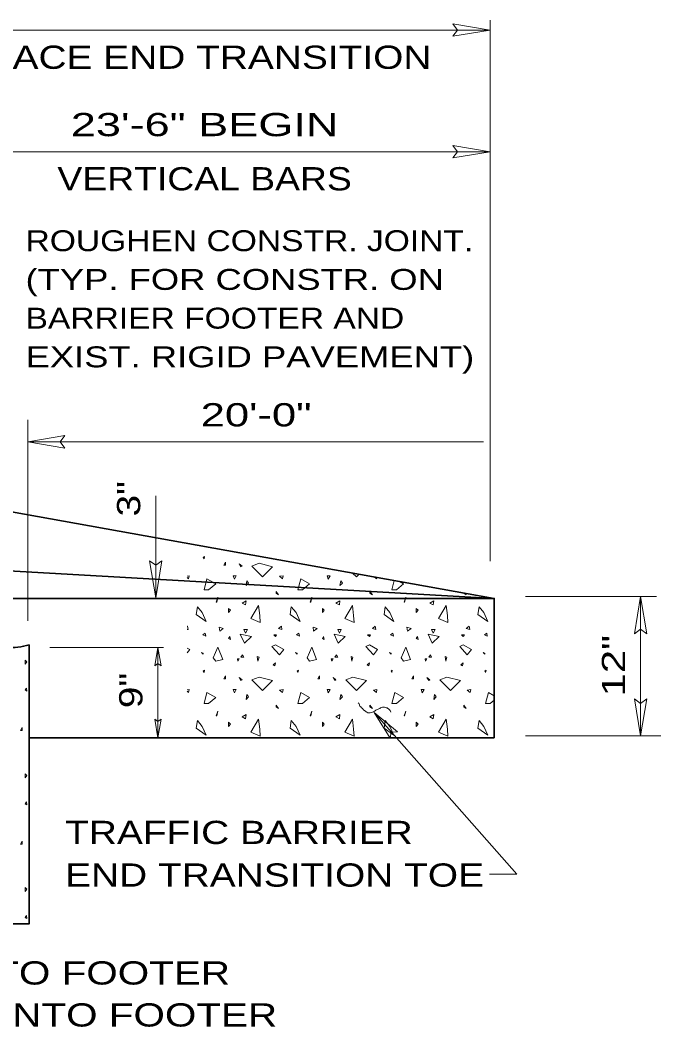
# Model space of a CAD drawing. Extents: x -15.1 to -7.9, y 13.6 to 23.8.
# Drawn here: x -9.819 to -8.165, y 17.024 to 19.625 of the extents above; entities that cross this region are included whole.
import ezdxf
from ezdxf.enums import TextEntityAlignment as Align

# ---------------------------------------------------------------- set-up
doc = ezdxf.new("R2010")
doc.units = 0
doc.header["$LTSCALE"] = 0.024
for name, color, linetype, lineweight in [('1', 7, 'Continuous', 35), ('10', 7, 'Continuous', 13), ('12', 7, 'Continuous', 53), ('6', 7, 'Continuous', 13)]:
    doc.layers.add(name, color=color, linetype=linetype, lineweight=lineweight)

msp = doc.modelspace()

# ---------------------------------------------------------------- linework, layer by layer
at = {"layer": '1'}
for q in [(-11.27267, 18.28367), (-11.26617, 18.13083)]:
    msp.add_line((-8.59533, 18.13083), q, dxfattribs=at)
for points in [[(-8.59533, 17.77083), (-8.59533, 18.13083), (-11.26567, 18.61083)], [(-8.59533, 17.77083), (-9.7955, 17.77083), (-9.7955, 18.01083)], [(-9.7955, 17.77083), (-9.7955, 17.29067), (-11.26567, 17.29067)]]:
    msp.add_lwpolyline(points, dxfattribs=at)
msp.add_spline([(-9.7955, 18.01083), (-9.85317, 18.006), (-9.89217, 18.019), (-9.94717, 18.00933), (-9.9505, 18.00933), (-9.9925, 18.00933), (-10.02167, 18.01567), (-10.06383, 18.019), (-10.10283, 18.02217), (-10.13517, 18.0125), (-10.17083, 18.00283), (-10.213, 18.00283), (-10.2485, 18.006), (-10.2875, 18.00933), (-10.31983, 18.0125), (-10.3685, 18.01567), (-10.42033, 18.01567), (-10.456, 18.0125), (-10.48183, 18.0125), (-10.511, 18.0125), (-10.52083, 18.01567), (-10.57917, 18.02867), (-10.605, 18.03517), (-10.644, 18.03183), (-10.69583, 18.02867), (-10.72817, 18.0255), (-10.7605, 18.02867), (-10.81567, 18.02867), (-10.874, 18.03517), (-10.93233, 18.03517), (-10.98417, 18.03183), (-11.02633, 18.02867), (-11.07817, 18.03833), (-11.14617, 18.05117), (-11.2045, 18.048), (-11.23367, 18.0415), (-11.25967, 18.03517), (-11.26617, 18.03183)], degree=3, dxfattribs=at)
at = {"layer": '10'}
for p, q in [((-8.702, 19.61517), (-8.606, 19.59917)), ((-8.702, 19.61517), (-8.69, 19.59917)), ((-8.606, 18.227), (-8.606, 19.625)), ((-13.76867, 19.59917), (-8.606, 19.59917)), ((-8.702, 19.58317), (-8.606, 19.59917)), ((-8.702, 19.58317), (-8.69, 19.59917)), ((-8.702, 19.30117), (-8.606, 19.28517)), ((-8.702, 19.30117), (-8.69, 19.28517)), ((-10.09083, 19.28517), (-8.606, 19.28517)), ((-8.702, 19.26917), (-8.606, 19.28517)), ((-8.702, 19.26917), (-8.69, 19.28517)), ((-9.7995, 18.07283), (-9.7995, 18.5925)), ((-9.7035, 18.5515), (-9.7995, 18.5355)), ((-9.7035, 18.5515), (-9.7155, 18.5355)), ((-9.7995, 18.5355), (-8.62317, 18.5355)), ((-9.7035, 18.5195), (-9.7995, 18.5355)), ((-9.7035, 18.5195), (-9.7155, 18.5355)), ((-9.46917, 18.1325), (-9.46917, 18.39583)), ((-9.48517, 18.2285), (-9.46917, 18.1325)), ((-9.48517, 18.2285), (-9.46917, 18.2165)), ((-9.45317, 18.2285), (-9.46917, 18.1325)), ((-9.45317, 18.2285), (-9.46917, 18.2165)), ((-8.51467, 18.136), (-8.17667, 18.136)), ((-8.23367, 18.03983), (-8.21767, 18.136)), ((-8.21767, 17.77583), (-8.21767, 18.136)), ((-8.20167, 18.03983), (-8.21767, 18.136)), ((-8.23367, 18.03983), (-8.21767, 18.05183)), ((-8.20167, 18.03983), (-8.21767, 18.05183)), ((-9.7425, 18.0045), (-9.44933, 18.0045)), ((-9.4715, 17.9565), (-9.4635, 18.0045)), ((-9.4635, 18.0045), (-9.4635, 17.77083)), ((-9.4555, 17.9565), (-9.4635, 18.0045)), ((-9.4715, 17.9565), (-9.4635, 17.9625)), ((-9.4555, 17.9565), (-9.4635, 17.9625)), ((-8.23367, 17.87183), (-8.21767, 17.77583)), ((-8.23367, 17.87183), (-8.21767, 17.85983)), ((-8.20167, 17.87183), (-8.21767, 17.77583)), ((-8.20167, 17.87183), (-8.21767, 17.85983)), ((-9.4715, 17.81883), (-9.4635, 17.77083)), ((-9.4715, 17.81883), (-9.4635, 17.81283)), ((-9.4555, 17.81883), (-9.4635, 17.77083)), ((-9.4555, 17.81883), (-9.4635, 17.81283)), ((-8.53683, 17.41833), (-8.90567, 17.83583)), ((-8.86433, 17.76983), (-8.90567, 17.83583)), ((-8.84517, 17.78667), (-8.90567, 17.83583)), ((-8.86433, 17.76983), (-8.86117, 17.7855)), ((-8.84517, 17.78667), (-8.86117, 17.7855)), ((-8.51467, 17.77583), (-8.16533, 17.77583)), ((-8.6075, 17.41833), (-8.53683, 17.41833))]:
    msp.add_line(p, q, dxfattribs=at)
msp.add_spline([(-8.86267, 17.837), (-8.864, 17.84133), (-8.867, 17.84417), (-8.86983, 17.847), (-8.87417, 17.8485), (-8.8785, 17.84983), (-8.88417, 17.84983), (-8.893, 17.84567), (-8.89717, 17.84417), (-8.9045, 17.83983), (-8.916, 17.8355), (-8.92183, 17.8355), (-8.92617, 17.83833), (-8.93183, 17.84267), (-8.93767, 17.8485), (-8.942, 17.85283), (-8.94483, 17.86), (-8.94633, 17.8615)], degree=3, dxfattribs=at)
at = {"layer": '6'}
for points in [[(-9.34317, 18.23967), (-9.34633, 18.23683), (-9.3445, 18.2335)], [(-9.28867, 18.2245), (-9.293, 18.217), (-9.28867, 18.217)], [(-9.24917, 18.21267), (-9.24633, 18.21417), (-9.25383, 18.22017)], [(-9.20233, 18.22167), (-9.16733, 18.21267), (-9.19333, 18.18667), (-9.22067, 18.21417)], [(-9.33267, 18.15317), (-9.31433, 18.16867), (-9.337, 18.182), (-9.3445, 18.15317)], [(-9.269, 18.18967), (-9.266, 18.18067), (-9.26133, 18.18967)], [(-9.14933, 18.18817), (-9.14183, 18.182), (-9.14033, 18.18967)], [(-9.09033, 18.15317), (-9.072, 18.16867), (-9.09467, 18.182), (-9.10217, 18.15317)], [(-9.02667, 18.18967), (-9.02367, 18.18067), (-9.019, 18.18967)], [(-9.234, 18.17633), (-9.23583, 18.164), (-9.22967, 18.17017)], [(-8.99167, 18.17633), (-8.9935, 18.164), (-8.98733, 18.17017)], [(-9.31283, 18.1215), (-9.3115, 18.1215), (-9.3085, 18.13383)], [(-9.15833, 18.149), (-9.15833, 18.14417), (-9.15233, 18.14)], [(-9.0705, 18.1215), (-9.06917, 18.1215), (-9.06617, 18.13383)], [(-8.91617, 18.149), (-8.91617, 18.14417), (-8.91, 18.14)], [(-8.82817, 18.1215), (-8.82683, 18.1215), (-8.82383, 18.13383)], [(-9.3615, 18.10933), (-9.36433, 18.08983), (-9.33883, 18.0715), (-9.34917, 18.09417)], [(-9.28117, 18.105), (-9.28117, 18.09417), (-9.2765, 18.10033)], [(-9.24633, 18.11867), (-9.23733, 18.114), (-9.23583, 18.12483)], [(-9.20083, 18.08667), (-9.1995, 18.06867), (-9.2235, 18.079), (-9.20383, 18.1125)], [(-9.11917, 18.10933), (-9.122, 18.08983), (-9.0965, 18.0715), (-9.107, 18.09417)], [(-9.03883, 18.105), (-9.03883, 18.09417), (-9.03417, 18.10033)], [(-9.004, 18.11867), (-8.995, 18.114), (-8.9935, 18.12483)], [(-8.9585, 18.08667), (-8.95717, 18.06867), (-8.98133, 18.079), (-8.9615, 18.1125)], [(-8.87683, 18.10933), (-8.87967, 18.08983), (-8.85417, 18.0715), (-8.86467, 18.09417)], [(-8.7965, 18.105), (-8.7965, 18.09417), (-8.79183, 18.10033)], [(-8.76167, 18.11867), (-8.75267, 18.114), (-8.75117, 18.12483)], [(-8.71633, 18.08667), (-8.71483, 18.06867), (-8.739, 18.079), (-8.71917, 18.1125)], [(-8.6345, 18.10933), (-8.63733, 18.08983), (-8.61183, 18.0715), (-8.62233, 18.09417)], [(-9.30533, 18.05633), (-9.30383, 18.046), (-9.29483, 18.0535)], [(-9.14467, 18.05967), (-9.15233, 18.0535), (-9.14333, 18.05033)], [(-9.063, 18.05633), (-9.0615, 18.046), (-9.0525, 18.0535)], [(-8.90233, 18.05967), (-8.91, 18.0535), (-8.901, 18.05033)], [(-8.82067, 18.05633), (-8.81917, 18.046), (-8.81017, 18.0535)], [(-8.66017, 18.05967), (-8.66767, 18.0535), (-8.65867, 18.05033)], [(-9.34783, 18.037), (-9.34017, 18.03367), (-9.34167, 18.04133)], [(-9.28117, 18.0275), (-9.2765, 18.02467), (-9.278, 18.03233)], [(-9.251, 18.03833), (-9.24017, 18.01567), (-9.22217, 18.03233)], [(-9.2415, 18.05033), (-9.23733, 18.04133), (-9.2325, 18.05033)], [(-9.1645, 18.037), (-9.15983, 18.03233), (-9.157, 18.037)], [(-9.1055, 18.037), (-9.098, 18.03367), (-9.09933, 18.04133)], [(-9.03883, 18.0275), (-9.03417, 18.02467), (-9.03567, 18.03233)], [(-9.00867, 18.03833), (-8.99783, 18.01567), (-8.97983, 18.03233)], [(-8.99933, 18.05033), (-8.995, 18.04133), (-8.99033, 18.05033)], [(-8.92217, 18.037), (-8.9175, 18.03233), (-8.91467, 18.037)], [(-8.86317, 18.037), (-8.85567, 18.03367), (-8.857, 18.04133)], [(-8.7965, 18.0275), (-8.79183, 18.02467), (-8.79333, 18.03233)], [(-8.76633, 18.03833), (-8.7555, 18.01567), (-8.7375, 18.03233)], [(-8.757, 18.05033), (-8.75267, 18.04133), (-8.748, 18.05033)], [(-8.67983, 18.037), (-8.67517, 18.03233), (-8.67233, 18.037)], [(-8.62083, 18.037), (-8.61333, 18.03367), (-8.61467, 18.04133)], [(-9.31433, 17.9685), (-9.29633, 17.97317), (-9.3085, 18.00483), (-9.3205, 17.97783)], [(-9.16917, 18.00667), (-9.14933, 17.9855), (-9.13867, 17.99883), (-9.15983, 18.011)], [(-9.072, 17.9685), (-9.054, 17.97317), (-9.06617, 18.00483), (-9.07817, 17.97783)], [(-8.92683, 18.00667), (-8.90717, 17.9855), (-8.89633, 17.99883), (-8.9175, 18.011)], [(-8.82967, 17.9685), (-8.81167, 17.97317), (-8.82383, 18.00483), (-8.83583, 17.97783)], [(-8.6845, 18.00667), (-8.66483, 17.9855), (-8.654, 17.99883), (-8.67517, 18.011)], [(-9.34633, 17.98983), (-9.35067, 17.99117), (-9.34633, 17.98683)], [(-9.2585, 17.97467), (-9.257, 17.9685), (-9.25383, 17.97467)], [(-9.24483, 17.9855), (-9.2415, 17.97933), (-9.24917, 17.97933)], [(-9.207, 17.98083), (-9.20517, 17.9685), (-9.20233, 17.97933)], [(-9.104, 17.98983), (-9.10833, 17.99117), (-9.104, 17.98683)], [(-9.01617, 17.97467), (-9.01467, 17.9685), (-9.0115, 17.97467)], [(-9.0025, 17.9855), (-8.99933, 17.97933), (-9.00683, 17.97933)], [(-8.96467, 17.98083), (-8.96283, 17.9685), (-8.96, 17.97933)], [(-8.86167, 17.98983), (-8.866, 17.99117), (-8.86167, 17.98683)], [(-8.77383, 17.97467), (-8.7725, 17.9685), (-8.76917, 17.97467)], [(-8.76017, 17.9855), (-8.757, 17.97933), (-8.7645, 17.97933)], [(-8.72233, 17.98083), (-8.7205, 17.9685), (-8.71767, 17.97933)], [(-8.61933, 17.98983), (-8.62367, 17.99117), (-8.61933, 17.98683)], [(-9.80633, 17.97183), (-9.80633, 17.96117), (-9.80167, 17.96717)], [(-9.166, 17.9595), (-9.16167, 17.95667), (-9.15983, 17.96417)], [(-8.92367, 17.9595), (-8.91933, 17.95667), (-8.9175, 17.96417)], [(-8.68133, 17.9595), (-8.677, 17.95667), (-8.67517, 17.96417)], [(-9.34317, 17.94583), (-9.34633, 17.943), (-9.3445, 17.93967)], [(-9.28867, 17.93067), (-9.293, 17.92317), (-9.28867, 17.92317)], [(-9.24917, 17.91883), (-9.24633, 17.92033), (-9.25383, 17.92633)], [(-9.20233, 17.92783), (-9.16733, 17.91883), (-9.19333, 17.893), (-9.22067, 17.92033)], [(-9.10083, 17.94583), (-9.104, 17.943), (-9.10217, 17.93967)], [(-9.0465, 17.93067), (-9.05067, 17.92317), (-9.0465, 17.92317)], [(-9.00683, 17.91883), (-9.004, 17.92033), (-9.0115, 17.92633)], [(-8.96, 17.92783), (-8.92517, 17.91883), (-8.951, 17.893), (-8.97833, 17.92033)], [(-8.8585, 17.94583), (-8.86167, 17.943), (-8.86, 17.93967)], [(-8.80417, 17.93067), (-8.8085, 17.92317), (-8.80417, 17.92317)], [(-8.7645, 17.91883), (-8.76167, 17.92033), (-8.76917, 17.92633)], [(-8.71767, 17.92783), (-8.68283, 17.91883), (-8.70867, 17.893), (-8.736, 17.92033)], [(-8.61617, 17.94583), (-8.61933, 17.943), (-8.61767, 17.93967)], [(-9.80633, 17.8945), (-9.80167, 17.89167), (-9.803, 17.89917)], [(-9.269, 17.89583), (-9.266, 17.88683), (-9.26133, 17.89583)], [(-9.14933, 17.89433), (-9.14183, 17.88817), (-9.14033, 17.89583)], [(-9.02667, 17.89583), (-9.02367, 17.88683), (-9.019, 17.89583)], [(-8.90717, 17.89433), (-8.8995, 17.88817), (-8.89817, 17.89583)], [(-8.78433, 17.89583), (-8.7815, 17.88683), (-8.77667, 17.89583)], [(-8.66483, 17.89433), (-8.65717, 17.88817), (-8.65583, 17.89583)], [(-9.33267, 17.8595), (-9.31433, 17.875), (-9.337, 17.88817), (-9.3445, 17.8595)], [(-9.234, 17.8825), (-9.23583, 17.87017), (-9.22967, 17.87633)], [(-9.09033, 17.8595), (-9.072, 17.875), (-9.09467, 17.88817), (-9.10217, 17.8595)], [(-8.99167, 17.8825), (-8.9935, 17.87017), (-8.98733, 17.87633)], [(-8.848, 17.8595), (-8.82967, 17.875), (-8.85233, 17.88817), (-8.86, 17.8595)], [(-8.74933, 17.8825), (-8.75117, 17.87017), (-8.745, 17.87633)], [(-9.15833, 17.85517), (-9.15833, 17.8505), (-9.15233, 17.84617)], [(-8.91617, 17.85517), (-8.91617, 17.8505), (-8.91, 17.84617)], [(-8.67383, 17.85517), (-8.67383, 17.8505), (-8.66767, 17.84617)], [(-9.31283, 17.82783), (-9.3115, 17.82783), (-9.3085, 17.84)], [(-9.24633, 17.82483), (-9.23733, 17.82017), (-9.23583, 17.831)], [(-9.20083, 17.79283), (-9.1995, 17.77483), (-9.2235, 17.78533), (-9.20383, 17.81867)], [(-9.0705, 17.82783), (-9.06917, 17.82783), (-9.06617, 17.84)], [(-9.004, 17.82483), (-8.995, 17.82017), (-8.9935, 17.831)], [(-8.9585, 17.79283), (-8.95717, 17.77483), (-8.98133, 17.78533), (-8.9615, 17.81867)], [(-8.82817, 17.82783), (-8.82683, 17.82783), (-8.82383, 17.84)], [(-8.76167, 17.82483), (-8.75267, 17.82017), (-8.75117, 17.831)], [(-8.71633, 17.79283), (-8.71483, 17.77483), (-8.739, 17.78533), (-8.71917, 17.81867)], [(-9.81383, 17.79767), (-9.81817, 17.79), (-9.81383, 17.79)], [(-9.3615, 17.8155), (-9.36433, 17.796), (-9.33883, 17.77767), (-9.34917, 17.80033)], [(-9.28117, 17.81117), (-9.28117, 17.80033), (-9.2765, 17.8065)], [(-9.11917, 17.8155), (-9.122, 17.796), (-9.0965, 17.77767), (-9.107, 17.80033)], [(-9.03883, 17.81117), (-9.03883, 17.80033), (-9.03417, 17.8065)], [(-8.87683, 17.8155), (-8.87967, 17.796), (-8.85417, 17.77767), (-8.86467, 17.80033)], [(-8.7965, 17.81117), (-8.7965, 17.80033), (-8.79183, 17.8065)], [(-8.6345, 17.8155), (-8.63733, 17.796), (-8.61183, 17.77767), (-8.62233, 17.80033)], [(-9.80633, 17.67817), (-9.80633, 17.66733), (-9.80167, 17.67333)], [(-9.80633, 17.60067), (-9.80167, 17.59783), (-9.803, 17.60533)], [(-9.81383, 17.50383), (-9.81817, 17.49633), (-9.81383, 17.49633)], [(-9.80633, 17.38433), (-9.80633, 17.3735), (-9.80167, 17.37967)], [(-9.80633, 17.30683), (-9.80167, 17.304), (-9.803, 17.3115)]]:
    msp.add_lwpolyline(points, close=True, dxfattribs=at)
for points in [[(-9.38767, 18.18483), (-9.38417, 18.182), (-9.38267, 18.18967), (-9.38767, 18.18883)], [(-8.94417, 18.1935), (-8.951, 18.18667), (-8.96083, 18.1965)], [(-8.90517, 18.1865), (-8.8995, 18.182), (-8.89883, 18.18533)], [(-8.85367, 18.17733), (-8.86, 18.15317), (-8.848, 18.15317), (-8.82967, 18.16867), (-8.84017, 18.17483)], [(-8.67383, 18.145), (-8.67383, 18.14417), (-8.66767, 18.14), (-8.67067, 18.14433)], [(-9.38767, 18.051), (-9.38567, 18.05033), (-9.387, 18.05967), (-9.38767, 18.05917)], [(-9.38767, 17.9905), (-9.381, 17.99883), (-9.38767, 18.00267)], [(-9.38767, 17.891), (-9.38417, 17.88817), (-9.38267, 17.89583), (-9.38767, 17.895)], [(-8.59533, 17.8795), (-8.61, 17.88817), (-8.61767, 17.8595), (-8.60567, 17.8595), (-8.59533, 17.86817)]]:
    msp.add_lwpolyline(points, dxfattribs=at)

# ---------------------------------------------------------------- texts
at = {"layer": '12'}
for s, width, p in [('PAYMENT PER EACH FOR F SHAPE CONCRETE TRAFFIC BARRIER SINGLE FACE END TRANSITION', 1.25, (-11.15954, 19.49917)), ('23\'-6" BEGIN', 1.45, (-9.34292, 19.32517)), ('VERTICAL BARS', 1.2, (-9.34296, 19.18517)), ('20\'-0"', 1.4, (-9.20992, 18.57542))]:
    msp.add_text(s, height=0.06001, dxfattribs=dict(at, width=width)).set_placement(p, align=Align.CENTER)
for s, height, width, p in [('ROUGHEN CONSTR. JOINT.', 0.05401, 1.2, (-9.80517, 19.02808)), ('(TYP. FOR CONSTR. ON', 0.05401, 1.3, (-9.80517, 18.92808)), ('BARRIER FOOTER AND', 0.05401, 1.2, (-9.80517, 18.82808)), ('EXIST. RIGID PAVEMENT)', 0.05401, 1.3, (-9.80517, 18.72808)), ('TRAFFIC BARRIER', 0.06001, 1.25, (-9.703, 17.49642)), ('END TRANSITION TOE', 0.06001, 1.25, (-9.703, 17.38633)), ('9" FOOTER DEPTH - VERTICAL BARS TO EXTEND 6" INTO FOOTER', 0.06001, 1.3, (-12.62642, 17.13342)), ('24" FOOTER DEPTH - VERTICAL BARS TO EXTEND 21" INTO FOOTER', 0.06001, 1.3, (-12.62067, 17.02492))]:
    msp.add_text(s, height=height, dxfattribs=dict(at, width=width)).set_placement(p)
for s, width, p in [('3"', 1.25, (-9.50917, 18.38837)), ('12"', 1.35, (-8.25758, 17.95704)), ('9"', 1.25, (-9.5035, 17.89312))]:
    msp.add_text(s, height=0.06001, rotation=90, dxfattribs=dict(at, width=width)).set_placement(p, align=Align.CENTER)

doc.saveas('drawing.dxf')
